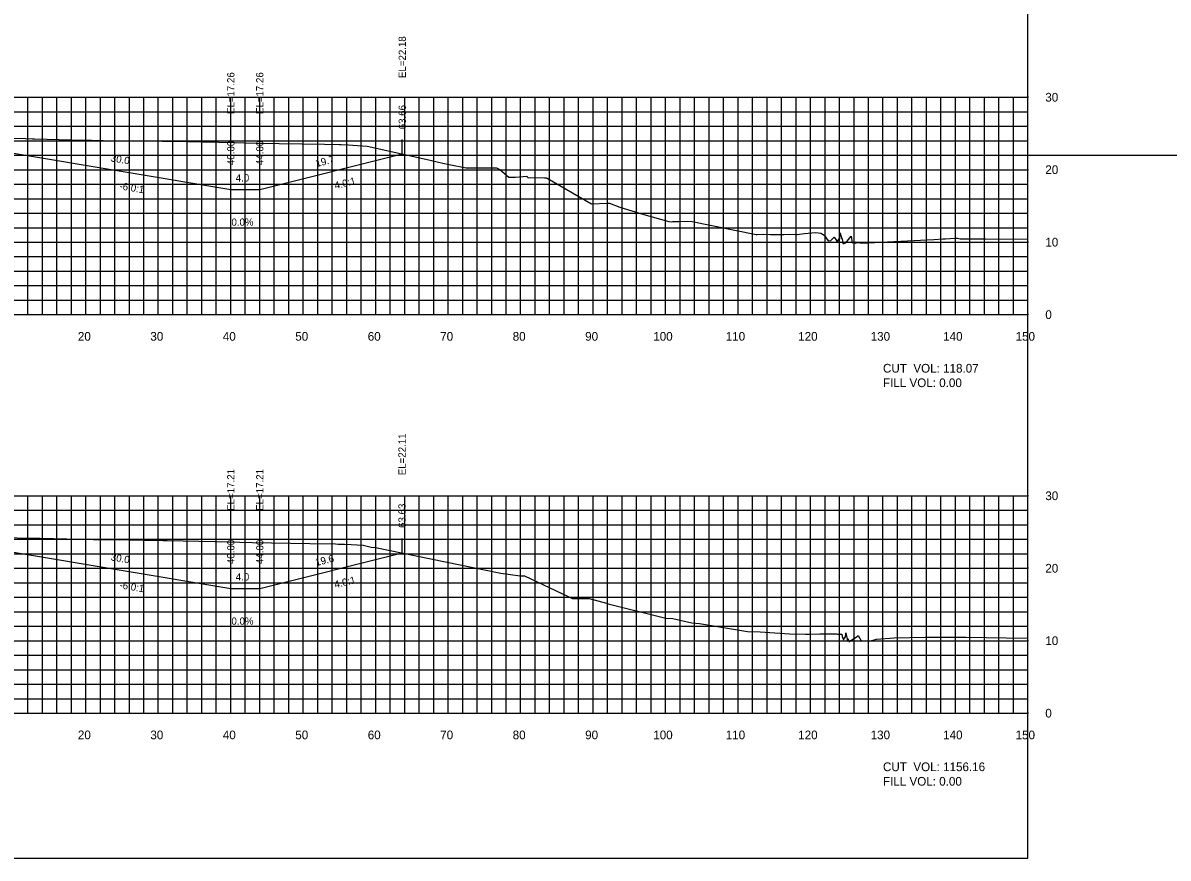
# Model space of a CAD drawing. Extents: x 1800976 to 1805104, y 250057 to 250580.
# Drawn here: x 1802642.3 to 1802800.3, y 250079.4 to 250194.7 of the extents above; entities that cross this region are included whole.
import ezdxf

# ---------------------------------------------------------------- set-up
doc = ezdxf.new("R2010")
doc.units = 0
for name, color, linetype in [('10', 7, 'Continuous'), ('3', 7, 'Continuous'), ('31', 7, 'Continuous'), ('4', 7, 'Continuous'), ('60', 7, 'Continuous'), ('ANNO-TXT', 7, 'Continuous'), ('CL-CNST', 7, 'Continuous'), ('Level 62', 7, 'Continuous'), ('M-ROADS', 7, 'Continuous')]:
    doc.layers.add(name, color=color, linetype=linetype)

msp = doc.modelspace()

# ---------------------------------------------------------------- linework, layer by layer
for p, q in [((1802694.66, 250176.61), (1802694.66, 250178.61)), ((1802671, 250171.7), (1802671, 250173.7)), ((1802675, 250171.7), (1802675, 250173.7)), ((1802694.63, 250121.55), (1802694.63, 250123.55)), ((1802671, 250116.64), (1802671, 250118.64)), ((1802675, 250116.64), (1802675, 250118.64))]:
    msp.add_line(p, q)
msp.add_lwpolyline([(1802481, 250079.43), (1802781, 250079.43), (1802781, 250269.43), (1802481, 250269.43)], close=True)
at = {"layer": '60'}
for p, q in [((1802781, 250154.43), (1802781, 250184.43)), ((1802781.06, 250184.43), (1802781, 250184.43)), ((1802781.06, 250174.43), (1802781, 250174.43)), ((1802781.06, 250164.43), (1802781, 250164.43)), ((1802481, 250154.43), (1802781, 250154.43)), ((1802651, 250154.37), (1802651, 250154.43)), ((1802661, 250154.37), (1802661, 250154.43)), ((1802671, 250154.37), (1802671, 250154.43)), ((1802681, 250154.37), (1802681, 250154.43)), ((1802691, 250154.37), (1802691, 250154.43)), ((1802701, 250154.37), (1802701, 250154.43)), ((1802711, 250154.37), (1802711, 250154.43)), ((1802721, 250154.37), (1802721, 250154.43)), ((1802731, 250154.37), (1802731, 250154.43)), ((1802741, 250154.37), (1802741, 250154.43)), ((1802751, 250154.37), (1802751, 250154.43)), ((1802761, 250154.37), (1802761, 250154.43)), ((1802771, 250154.37), (1802771, 250154.43)), ((1802781, 250154.37), (1802781, 250154.43)), ((1802781.06, 250154.43), (1802781, 250154.43)), ((1802781, 250099.43), (1802781, 250129.43)), ((1802781.06, 250129.43), (1802781, 250129.43)), ((1802781.06, 250119.43), (1802781, 250119.43)), ((1802781.06, 250109.43), (1802781, 250109.43)), ((1802481, 250099.43), (1802781, 250099.43)), ((1802651, 250099.37), (1802651, 250099.43)), ((1802661, 250099.37), (1802661, 250099.43)), ((1802671, 250099.37), (1802671, 250099.43)), ((1802681, 250099.37), (1802681, 250099.43)), ((1802691, 250099.37), (1802691, 250099.43)), ((1802701, 250099.37), (1802701, 250099.43)), ((1802711, 250099.37), (1802711, 250099.43)), ((1802721, 250099.37), (1802721, 250099.43)), ((1802731, 250099.37), (1802731, 250099.43)), ((1802741, 250099.37), (1802741, 250099.43)), ((1802751, 250099.37), (1802751, 250099.43)), ((1802761, 250099.37), (1802761, 250099.43)), ((1802771, 250099.37), (1802771, 250099.43)), ((1802781, 250099.37), (1802781, 250099.43)), ((1802781.06, 250099.43), (1802781, 250099.43))]:
    msp.add_line(p, q, dxfattribs=at)
at = {"layer": 'CL-CNST'}
for points in [[(1802601, 250177.76), (1802607, 250177.62), (1802631, 250177.1), (1802639, 250176.78), (1802641, 250176.7), (1802671, 250171.7), (1802675, 250171.7), (1802694.66, 250176.61)], [(1802601, 250122.7), (1802607, 250122.57), (1802631, 250122.04), (1802639, 250121.72), (1802641, 250121.64), (1802671, 250116.64), (1802675, 250116.64), (1802694.63, 250121.55)]]:
    msp.add_lwpolyline(points, dxfattribs=at)
at = {"layer": 'Level 62'}
for p, q in [((1802481, 250184.43), (1802781, 250184.43)), ((1802643, 250154.43), (1802643, 250184.43)), ((1802645, 250154.43), (1802645, 250184.43)), ((1802647, 250154.43), (1802647, 250184.43)), ((1802649, 250154.43), (1802649, 250184.43)), ((1802651, 250154.43), (1802651, 250184.43)), ((1802653, 250154.43), (1802653, 250184.43)), ((1802655, 250154.43), (1802655, 250184.43)), ((1802657, 250154.43), (1802657, 250184.43)), ((1802659, 250154.43), (1802659, 250184.43)), ((1802661, 250154.43), (1802661, 250184.43)), ((1802663, 250154.43), (1802663, 250184.43)), ((1802665, 250154.43), (1802665, 250184.43)), ((1802667, 250154.43), (1802667, 250184.43)), ((1802669, 250154.43), (1802669, 250184.43)), ((1802671, 250154.43), (1802671, 250184.43)), ((1802673, 250154.43), (1802673, 250184.43)), ((1802675, 250154.43), (1802675, 250184.43)), ((1802677, 250154.43), (1802677, 250184.43)), ((1802679, 250154.43), (1802679, 250184.43)), ((1802681, 250154.43), (1802681, 250184.43)), ((1802683, 250154.43), (1802683, 250184.43)), ((1802685, 250154.43), (1802685, 250184.43)), ((1802687, 250154.43), (1802687, 250184.43)), ((1802689, 250154.43), (1802689, 250184.43)), ((1802691, 250154.43), (1802691, 250184.43)), ((1802693, 250154.43), (1802693, 250184.43)), ((1802695, 250154.43), (1802695, 250184.43)), ((1802697, 250154.43), (1802697, 250184.43)), ((1802699, 250154.43), (1802699, 250184.43)), ((1802701, 250154.43), (1802701, 250184.43)), ((1802703, 250154.43), (1802703, 250184.43)), ((1802705, 250154.43), (1802705, 250184.43)), ((1802707, 250154.43), (1802707, 250184.43)), ((1802709, 250154.43), (1802709, 250184.43)), ((1802711, 250154.43), (1802711, 250184.43)), ((1802713, 250154.43), (1802713, 250184.43)), ((1802715, 250154.43), (1802715, 250184.43)), ((1802717, 250154.43), (1802717, 250184.43)), ((1802719, 250154.43), (1802719, 250184.43)), ((1802721, 250154.43), (1802721, 250184.43)), ((1802723, 250154.43), (1802723, 250184.43)), ((1802725, 250154.43), (1802725, 250184.43)), ((1802727, 250154.43), (1802727, 250184.43)), ((1802729, 250154.43), (1802729, 250184.43)), ((1802731, 250154.43), (1802731, 250184.43)), ((1802733, 250154.43), (1802733, 250184.43)), ((1802735, 250154.43), (1802735, 250184.43)), ((1802737, 250154.43), (1802737, 250184.43)), ((1802739, 250154.43), (1802739, 250184.43)), ((1802741, 250154.43), (1802741, 250184.43)), ((1802743, 250154.43), (1802743, 250184.43)), ((1802745, 250154.43), (1802745, 250184.43)), ((1802747, 250154.43), (1802747, 250184.43)), ((1802749, 250154.43), (1802749, 250184.43)), ((1802751, 250154.43), (1802751, 250184.43)), ((1802753, 250154.43), (1802753, 250184.43)), ((1802755, 250154.43), (1802755, 250184.43)), ((1802757, 250154.43), (1802757, 250184.43)), ((1802759, 250154.43), (1802759, 250184.43)), ((1802761, 250154.43), (1802761, 250184.43)), ((1802763, 250154.43), (1802763, 250184.43)), ((1802765, 250154.43), (1802765, 250184.43)), ((1802767, 250154.43), (1802767, 250184.43)), ((1802769, 250154.43), (1802769, 250184.43)), ((1802771, 250154.43), (1802771, 250184.43)), ((1802773, 250154.43), (1802773, 250184.43)), ((1802775, 250154.43), (1802775, 250184.43)), ((1802777, 250154.43), (1802777, 250184.43)), ((1802779, 250154.43), (1802779, 250184.43)), ((1802781, 250154.43), (1802781, 250184.43)), ((1802481, 250182.43), (1802781, 250182.43)), ((1802481, 250180.43), (1802781, 250180.43)), ((1802481, 250178.43), (1802781, 250178.43)), ((1802481, 250176.43), (1802929.9, 250176.43)), ((1802481, 250174.43), (1802781, 250174.43)), ((1802481, 250172.43), (1802781, 250172.43)), ((1802481, 250170.43), (1802781, 250170.43)), ((1802481, 250168.43), (1802781, 250168.43)), ((1802481, 250166.43), (1802781, 250166.43)), ((1802481, 250164.43), (1802781, 250164.43)), ((1802481, 250162.43), (1802781, 250162.43)), ((1802481, 250160.43), (1802781, 250160.43)), ((1802481, 250158.43), (1802781, 250158.43)), ((1802481, 250156.43), (1802781, 250156.43)), ((1802481, 250154.43), (1802781, 250154.43)), ((1802481, 250129.43), (1802781, 250129.43)), ((1802643, 250099.43), (1802643, 250129.43)), ((1802645, 250099.43), (1802645, 250129.43)), ((1802647, 250099.43), (1802647, 250129.43)), ((1802649, 250099.43), (1802649, 250129.43)), ((1802651, 250099.43), (1802651, 250129.43)), ((1802653, 250099.43), (1802653, 250129.43)), ((1802655, 250099.43), (1802655, 250129.43)), ((1802657, 250099.43), (1802657, 250129.43)), ((1802659, 250099.43), (1802659, 250129.43)), ((1802661, 250099.43), (1802661, 250129.43)), ((1802663, 250099.43), (1802663, 250129.43)), ((1802665, 250099.43), (1802665, 250129.43)), ((1802667, 250099.43), (1802667, 250129.43)), ((1802669, 250099.43), (1802669, 250129.43)), ((1802671, 250099.43), (1802671, 250129.43)), ((1802673, 250099.43), (1802673, 250129.43)), ((1802675, 250099.43), (1802675, 250129.43)), ((1802677, 250099.43), (1802677, 250129.43)), ((1802679, 250099.43), (1802679, 250129.43)), ((1802681, 250099.43), (1802681, 250129.43)), ((1802683, 250099.43), (1802683, 250129.43)), ((1802685, 250099.43), (1802685, 250129.43)), ((1802687, 250099.43), (1802687, 250129.43)), ((1802689, 250099.43), (1802689, 250129.43)), ((1802691, 250099.43), (1802691, 250129.43)), ((1802693, 250099.43), (1802693, 250129.43)), ((1802695, 250099.43), (1802695, 250129.43)), ((1802697, 250099.43), (1802697, 250129.43)), ((1802699, 250099.43), (1802699, 250129.43)), ((1802701, 250099.43), (1802701, 250129.43)), ((1802703, 250099.43), (1802703, 250129.43)), ((1802705, 250099.43), (1802705, 250129.43)), ((1802707, 250099.43), (1802707, 250129.43)), ((1802709, 250099.43), (1802709, 250129.43)), ((1802711, 250099.43), (1802711, 250129.43)), ((1802713, 250099.43), (1802713, 250129.43)), ((1802715, 250099.43), (1802715, 250129.43)), ((1802717, 250099.43), (1802717, 250129.43)), ((1802719, 250099.43), (1802719, 250129.43)), ((1802721, 250099.43), (1802721, 250129.43)), ((1802723, 250099.43), (1802723, 250129.43)), ((1802725, 250099.43), (1802725, 250129.43)), ((1802727, 250099.43), (1802727, 250129.43)), ((1802729, 250099.43), (1802729, 250129.43)), ((1802731, 250099.43), (1802731, 250129.43)), ((1802733, 250099.43), (1802733, 250129.43)), ((1802735, 250099.43), (1802735, 250129.43)), ((1802737, 250099.43), (1802737, 250129.43)), ((1802739, 250099.43), (1802739, 250129.43)), ((1802741, 250099.43), (1802741, 250129.43)), ((1802743, 250099.43), (1802743, 250129.43)), ((1802745, 250099.43), (1802745, 250129.43)), ((1802747, 250099.43), (1802747, 250129.43)), ((1802749, 250099.43), (1802749, 250129.43)), ((1802751, 250099.43), (1802751, 250129.43)), ((1802753, 250099.43), (1802753, 250129.43)), ((1802755, 250099.43), (1802755, 250129.43)), ((1802757, 250099.43), (1802757, 250129.43)), ((1802759, 250099.43), (1802759, 250129.43)), ((1802761, 250099.43), (1802761, 250129.43)), ((1802763, 250099.43), (1802763, 250129.43)), ((1802765, 250099.43), (1802765, 250129.43)), ((1802767, 250099.43), (1802767, 250129.43)), ((1802769, 250099.43), (1802769, 250129.43)), ((1802771, 250099.43), (1802771, 250129.43)), ((1802773, 250099.43), (1802773, 250129.43)), ((1802775, 250099.43), (1802775, 250129.43)), ((1802777, 250099.43), (1802777, 250129.43)), ((1802779, 250099.43), (1802779, 250129.43)), ((1802781, 250099.43), (1802781, 250129.43)), ((1802481, 250127.43), (1802781, 250127.43)), ((1802481, 250125.43), (1802781, 250125.43)), ((1802481, 250123.43), (1802781, 250123.43)), ((1802481, 250121.43), (1802781, 250121.43)), ((1802481, 250119.43), (1802781, 250119.43)), ((1802481, 250117.43), (1802781, 250117.43)), ((1802481, 250115.43), (1802781, 250115.43)), ((1802481, 250113.43), (1802781, 250113.43)), ((1802481, 250111.43), (1802781, 250111.43)), ((1802481, 250109.43), (1802781, 250109.43)), ((1802481, 250107.43), (1802781, 250107.43)), ((1802481, 250105.43), (1802781, 250105.43)), ((1802481, 250103.43), (1802781, 250103.43)), ((1802481, 250101.43), (1802781, 250101.43)), ((1802481, 250099.43), (1802781, 250099.43))]:
    msp.add_line(p, q, dxfattribs=at)
at = {"layer": 'M-ROADS'}
for points in [[(1802635.41, 250178.88), (1802642.66, 250178.72), (1802643.65, 250178.68), (1802643.91, 250178.68), (1802648.97, 250178.57), (1802651.12, 250178.52), (1802651.79, 250178.51), (1802653.37, 250178.48), (1802657.65, 250178.4), (1802658.92, 250178.4), (1802661.5, 250178.38), (1802662.02, 250178.38), (1802662.75, 250178.37), (1802671.53, 250178.18), (1802674.55, 250178.11), (1802683.95, 250177.96), (1802685.98, 250177.93), (1802686.21, 250177.91), (1802687.23, 250177.86), (1802687.83, 250177.82), (1802689.82, 250177.7), (1802697.9, 250175.88), (1802700.25, 250175.34), (1802701.12, 250175.15), (1802703.5, 250174.71), (1802705.3, 250174.71), (1802706.86, 250174.71), (1802707.68, 250174.71), (1802708.14, 250174.47), (1802709.38, 250173.41), (1802710.29, 250173.39), (1802711.83, 250173.56), (1802711.87, 250173.51), (1802712.03, 250173.3), (1802712.42, 250173.34), (1802714.3, 250173.3), (1802714.54, 250173.3), (1802714.63, 250173.27), (1802714.68, 250173.25), (1802720.76, 250169.73), (1802722.95, 250169.79), (1802723.28, 250169.8), (1802724.67, 250169.24), (1802728.02, 250168.26), (1802731.44, 250167.26), (1802731.86, 250167.25), (1802731.98, 250167.26), (1802732.84, 250167.26), (1802734.44, 250167.35), (1802743.51, 250165.48), (1802743.61, 250165.46), (1802743.63, 250165.47), (1802744.5, 250165.53), (1802745.48, 250165.47), (1802745.83, 250165.49), (1802746.34, 250165.48), (1802747.33, 250165.48), (1802748.05, 250165.52), (1802749.13, 250165.49), (1802749.17, 250165.48), (1802750.16, 250165.63), (1802751.68, 250165.76), (1802752.43, 250165.69), (1802752.88, 250165.4), (1802753.42, 250164.63), (1802753.8, 250164.67), (1802754.27, 250165.13), (1802754.58, 250164.67), (1802754.61, 250164.45), (1802754.62, 250164.4), (1802754.96, 250164.91), (1802755.03, 250164.84), (1802755.08, 250165.74), (1802755.1, 250165.68), (1802755.33, 250164.89), (1802755.35, 250164.93), (1802755.48, 250164.26), (1802755.54, 250164.28), (1802755.55, 250164.22), (1802755.62, 250164.25), (1802755.72, 250164.32), (1802755.73, 250164.34), (1802755.86, 250164.34), (1802756.6, 250165.26), (1802756.63, 250165.26), (1802756.76, 250164.35), (1802756.9, 250164.37), (1802757.05, 250164.5), (1802757.11, 250164.39), (1802757.13, 250164.38), (1802757.17, 250164.3), (1802757.43, 250164.37), (1802757.44, 250164.4), (1802757.51, 250164.37), (1802757.84, 250164.36), (1802758.57, 250164.33), (1802758.9, 250164.35), (1802768, 250164.82), (1802769.25, 250164.87), (1802769.36, 250164.88), (1802769.63, 250164.9), (1802770.91, 250164.96), (1802771.22, 250164.98), (1802771.24, 250164.99), (1802771.29, 250164.96), (1802771.65, 250164.91), (1802772.11, 250164.9), (1802772.14, 250164.9), (1802774.14, 250164.9), (1802775.2, 250164.9), (1802781, 250164.85)], [(1802637.58, 250123.74), (1802643.43, 250123.6), (1802644.21, 250123.6), (1802644.68, 250123.59), (1802652.05, 250123.41), (1802652.55, 250123.4), (1802652.9, 250123.4), (1802657.11, 250123.33), (1802659.04, 250123.31), (1802660.95, 250123.29), (1802661.67, 250123.28), (1802662.2, 250123.28), (1802668.82, 250123.11), (1802674, 250122.99), (1802681.91, 250122.84), (1802685.43, 250122.78), (1802685.82, 250122.77), (1802686.68, 250122.74), (1802687.63, 250122.7), (1802689.26, 250122.61), (1802690.39, 250122.35), (1802690.99, 250122.29), (1802708.27, 250118.77), (1802710.92, 250118.4), (1802711.15, 250118.4), (1802711.51, 250118.4), (1802717.56, 250115.51), (1802718.09, 250115.25), (1802720.46, 250115.25), (1802722.85, 250114.62), (1802723.06, 250114.54), (1802731.03, 250112.55), (1802731.98, 250112.5), (1802734.63, 250111.9), (1802735.66, 250111.8), (1802742.32, 250110.68), (1802744.04, 250110.66), (1802748.09, 250110.4), (1802750.31, 250110.35), (1802750.84, 250110.32), (1802752.3, 250110.38), (1802754.59, 250110.37), (1802754.73, 250110.33), (1802755.11, 250110.34), (1802755.34, 250110.35), (1802755.38, 250110.01), (1802755.53, 250109.56), (1802755.76, 250109.92), (1802755.82, 250109.86), (1802755.85, 250110.5), (1802756.07, 250109.64), (1802756.11, 250109.51), (1802756.2, 250109.68), (1802756.27, 250109.31), (1802756.34, 250109.34), (1802756.35, 250109.3), (1802756.44, 250109.34), (1802756.44, 250109.35), (1802756.48, 250109.34), (1802756.55, 250109.44), (1802757.42, 250110.02), (1802757.57, 250110.16), (1802757.99, 250109.43), (1802758.01, 250109.42), (1802758.04, 250109.37), (1802758.23, 250109.42), (1802758.74, 250109.42), (1802759.12, 250109.35), (1802760.1, 250109.64), (1802762.54, 250109.85), (1802766.84, 250109.9), (1802768.12, 250109.9), (1802770.16, 250109.9), (1802770.96, 250109.91), (1802772.03, 250109.93), (1802772.06, 250109.94), (1802772.08, 250109.93), (1802772.47, 250109.93), (1802777.99, 250109.83), (1802781, 250109.8)]]:
    msp.add_lwpolyline(points, dxfattribs=at)

# ---------------------------------------------------------------- texts
for s, rotation, p in [('4.0:1', 14.0362, (1802685.44, 250171.73)), ('-6.0:1', 350.5377, (1802655.59, 250171.73)), ('4.0:1', 14.0362, (1802685.42, 250116.67)), ('-6.0:1', 350.5377, (1802655.59, 250116.67))]:
    msp.add_text(s, height=1, rotation=rotation).set_placement(p)
at = {"layer": '10'}
for s, p in [('20', (1802649.9, 250150.83)), ('30', (1802659.9, 250150.83)), ('40', (1802669.9, 250150.83)), ('50', (1802679.9, 250150.83)), ('60', (1802689.9, 250150.83)), ('70', (1802699.9, 250150.83)), ('80', (1802709.9, 250150.83)), ('90', (1802719.9, 250150.83)), ('100', (1802729.3, 250150.83)), ('110', (1802739.3, 250150.83)), ('120', (1802749.3, 250150.83)), ('130', (1802759.3, 250150.83)), ('140', (1802769.3, 250150.83)), ('150', (1802779.3, 250150.83)), ('20', (1802649.9, 250095.83)), ('30', (1802659.9, 250095.83)), ('40', (1802669.9, 250095.83)), ('50', (1802679.9, 250095.83)), ('60', (1802689.9, 250095.83)), ('70', (1802699.9, 250095.83)), ('80', (1802709.9, 250095.83)), ('90', (1802719.9, 250095.83)), ('100', (1802729.3, 250095.83)), ('110', (1802739.3, 250095.83)), ('120', (1802749.3, 250095.83)), ('130', (1802759.3, 250095.83)), ('140', (1802769.3, 250095.83)), ('150', (1802779.3, 250095.83))]:
    msp.add_text(s, height=1.2, dxfattribs=at).set_placement(p)
at = {"layer": '3'}
for s, p in [('EL=22.18', (1802695.16, 250187.08)), ('EL=17.26', (1802671.5, 250182.12)), ('EL=17.26', (1802675.5, 250182.12)), ('63.66', (1802695.16, 250180.01)), ('40.00', (1802671.5, 250175.07)), ('44.00', (1802675.5, 250175.07)), ('EL=22.11', (1802695.13, 250132.27)), ('EL=17.21', (1802671.5, 250127.36)), ('EL=17.21', (1802675.5, 250127.36)), ('63.63', (1802695.13, 250125)), ('40.00', (1802671.5, 250120.01)), ('44.00', (1802675.5, 250120.01))]:
    msp.add_text(s, height=1, rotation=90, dxfattribs=at).set_placement(p)
at = {"layer": '31'}
for s, p in [('30', (1802783.4, 250183.83)), ('20', (1802783.4, 250173.83)), ('10', (1802783.4, 250163.83)), ('0', (1802783.4, 250153.83)), ('30', (1802783.4, 250128.83)), ('20', (1802783.4, 250118.83)), ('10', (1802783.4, 250108.83)), ('0', (1802783.4, 250098.83))]:
    msp.add_text(s, height=1.2, dxfattribs=at).set_placement(p)
at = {"layer": '4'}
for s, rotation, p in [('30.0', 350.5377, (1802654.39, 250175.58)), ('19.7', 14.0362, (1802682.84, 250174.79)), ('30.0', 350.5377, (1802654.39, 250120.52)), ('19.6', 14.0362, (1802682.8, 250119.72))]:
    msp.add_text(s, height=1, rotation=rotation, dxfattribs=at).set_placement(p)
for s, p in [('4.0', (1802671.68, 250172.8)), ('0.0%', (1802671.09, 250166.7)), ('4.0', (1802671.68, 250117.74)), ('0.0%', (1802671.09, 250111.64))]:
    msp.add_text(s, height=1, dxfattribs=at).set_placement(p)
at = {"layer": 'ANNO-TXT'}
for s, p in [('CUT  VOL: 118.07', (1802761, 250146.43)), ('FILL VOL: 0.00', (1802761, 250144.43)), ('CUT  VOL: 1156.16', (1802761, 250091.43)), ('FILL VOL: 0.00', (1802761, 250089.43))]:
    msp.add_text(s, height=1.2, dxfattribs=at).set_placement(p)

doc.saveas('drawing.dxf')
